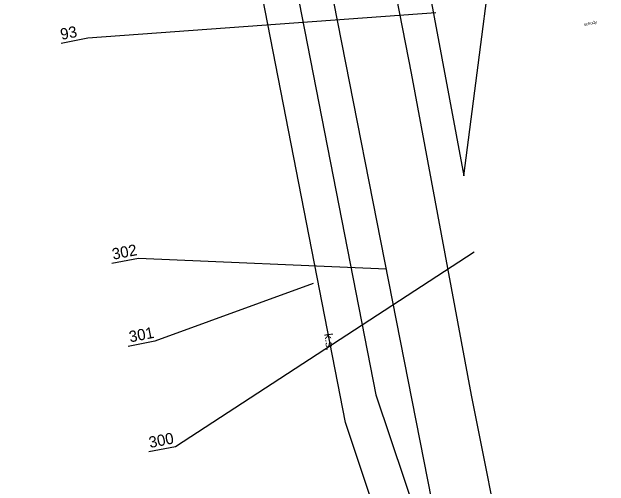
# Model space of a CAD drawing. Extents: x -545967 to -545044, y -1122650 to -1118491.
# Drawn here: x -545736.2 to -545636.3, y -1119477.8 to -1119398.5 of the extents above; entities that cross this region are included whole.
import ezdxf

# ---------------------------------------------------------------- set-up
doc = ezdxf.new("R2010")
doc.units = 0
for name, color, linetype in [('osvětlené plochy-hodnota-obrys', 7, 'Continuous'), ('so180602', 7, 'Continuous'), ('Vrstva 63', 7, 'Continuous')]:
    doc.layers.add(name, color=color, linetype=linetype)

msp = doc.modelspace()

# ---------------------------------------------------------------- linework, layer by layer
at = {"layer": 'osvětlené plochy-hodnota-obrys'}
for points in [[(-545700.341, -1119250.428), (-545705.955, -1119221.665), (-545699.039, -1119220.315), (-545660.607, -1119425.918), (-545653.752, -1119372.856), (-545653.095, -1119348.321), (-545657.119, -1119319.988), (-545685.945, -1119192.198), (-545694.33, -1119168.5)], [(-545664.282, -1119515.639), (-545680.447, -1119467.233), (-545736.202, -1119180.74), (-545730.573, -1119179.645)], [(-545730.573, -1119179.645), (-545675.345, -1119462.605), (-545660.82, -1119505.941)], [(-545716.386, -1119223.717), (-545705.994, -1119221.66), (-545669.439, -1119408.759), (-545659.4, -1119462.635), (-545647.69, -1119521.347), (-545640.519, -1119558.729), (-545633.585, -1119589.698), (-545629.517, -1119613.814), (-545623.042, -1119645.057), (-545619.034, -1119667.556), (-545607.519, -1119727.517)], [(-545610.895, -1119760.665), (-545622.836, -1119699.488), (-545637.26, -1119626.872), (-545653.542, -1119543.449), (-545716.386, -1119223.717)]]:
    msp.add_lwpolyline(points, dxfattribs=at)
at = {"layer": 'Vrstva 63'}
for p, q in [((-545665.307, -1119398.66), (-545723.536, -1119402.905)), ((-545723.536, -1119402.905), (-545727.98, -1119403.769)), ((-545658.91, -1119438.714), (-545708.862, -1119471.264)), ((-545715.029, -1119439.755), (-545719.473, -1119440.619)), ((-545673.644, -1119441.543), (-545715.029, -1119439.755)), ((-545685.853, -1119443.95), (-545712.316, -1119453.615)), ((-545712.316, -1119453.615), (-545716.761, -1119454.479)), ((-545708.862, -1119471.264), (-545713.306, -1119472.129))]:
    msp.add_line(p, q, dxfattribs=at)

# ---------------------------------------------------------------- texts
at = {"layer": 'so180602'}
for s, p in [('93', (-545727.919, -1119403.189)), ('302', (-545719.271, -1119439.98)), ('301', (-545716.433, -1119453.816)), ('300', (-545713.118, -1119471.492))]:
    msp.add_text(s, height=1.875, rotation=10.99553, dxfattribs=at).set_placement(p)
at = {"layer": 'Vrstva 63'}
for s, height, rotation, p in [('schody', 0.5, 11.71584, (-545640.507, -1119400.86)), ('k.s.', 1.3705, 277.81795, (-545683.974, -1119452.395))]:
    msp.add_text(s, height=height, rotation=rotation, dxfattribs=at).set_placement(p)

doc.saveas('drawing.dxf')
